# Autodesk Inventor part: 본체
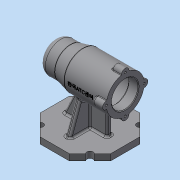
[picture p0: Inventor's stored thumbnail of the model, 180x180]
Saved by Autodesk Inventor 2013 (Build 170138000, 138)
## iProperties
Created: 2019-12
Part Number: 본체
Material: 일반
Document SubType Name: Modeling
Designer: Administrator
Density: 1 g/cm^3
Mass: 268.817 g
Surface Area: 714.69 cm^2
Volume: 268.817 cm^3
Author: Administrator
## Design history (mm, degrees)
sketch "스케치1"
  geometry: L1 (23.196, 56)-(56, 23.196); L2 (56, 23.196)-(56, -23.196); L3 (56, -23.196)-(23.196, -56); L4 (23.196, -56)-(-23.196, -56); L5 (-23.196, -56)-(-56, -23.196); L6 (-56, -23.196)-(-56, 23.196); L7 (-56, 23.196)-(-23.196, 56); L8 (-23.196, 56)-(23.196, 56); 3 further points
  constraints: 16 end point, 1 coincident, 1 midpoint, 1 vertical alignment, 17 other
  dimensions: "d2" = 56 distance from line of point (0, 0) L8
extrude "돌출1" new body sketch "스케치1" distance "d3" = 10; taper "d4" = 0 deg
sketch "스케치2"
  geometry: L1 (-56, 80)-(56, 80); L2 (-56, 0)-(-56, 10) reference; L3 (-56, 80)-(-56, 110); L4 (-56, 110)-(11, 110); L5 (11, 110)-(31, 105); L6 (31, 105)-(56, 105); L7 (56, 80)-(56, 105); 1 further point
  constraints: 12 end point, 2 perpendicular, 1 collinear, 1 horizontal, 1 parallel, 1 vertical alignment
  dimensions: "d5" = 112 distance of L1.start L1.end; "d7" = 80 vertical distance of point (0, 0) L1.start; "d8" = 50 diameter of L6 L1; "d9" = 60 diameter of L4 L1; "d10" = 45 horizontal distance of L1.end L4.end; "d11" = 25 horizontal distance of L1.end L5.end
revolve "회전1" sketch "스케치2" stored, may be unused: angle "d12" = 90 deg
sketch "스케치4"
  geometry: L1 (-23.196, -56)-(23.196, -56) reference; L2 (4, -36)-(-4, -36); L3 (-4, -36)-(-4, 36); L4 (-4, 36)-(4, 36); L5 (4, 36)-(4, -36); L6 (4, -36)-(-4, 36); L7 (-4, -36)-(4, 36); 3 further points
  constraints: 12 end point, 3 midpoint, 2 parallel, 1 coincident, 1 horizontal, 1 perpendicular
  dimensions: "d19" = 8 distance of L3.end L4.end; "d21" = 20 distance between parallel lines of L1 L2
extrude "돌출2" join sketch "스케치4" distance "d22" = 70; taper "d23" = 0 deg
feature "면 기울기1" dims angle "d24" = 20 deg
sketch "스케치5"
  geometry: L1 (-56, 23.196)-(-56, -23.196) reference; L2 (56, -23.196)-(56, 23.196) reference; L3 (-38, 4)-(31, 4); L4 (31, 4)-(31, -4); L5 (31, -4)-(-38, -4); L6 (-38, -4)-(-38, 4); 2 further points
  constraints: 8 end point, 2 parallel, 1 horizontal, 1 horizontal alignment, 1 midpoint, 1 perpendicular
  dimensions: "d25" = 18 distance between parallel lines of L1 L6; "d26" = 25 distance between parallel lines of L2 L4; "d27" = 8 distance between parallel lines of L3 L5
extrude "돌출3" join sketch "스케치5" distance "d28" = 70; taper "d29" = 0 deg
feature "면 기울기2" dims angle "d30" = 25 deg
sketch "스케치6"
  geometry: C1 r 30 at (0, 0) reference; C2 r 6 at (0, 30); 1 further point
  constraints: 1 centre point, 1 vertical alignment
  dimensions: "d31" = 12 diameter of C2; "d33" = 30 distance of C1.centre C2.centre
extrude "돌출4" join sketch "스케치6" distance "d34" = 16; taper "d35" = 0 deg
fillet "모깎기1" dims "d36" = 3
fillet "모깎기2" dims "d37" = 1
sketch "스케치7"
  geometry: A1 r 6 centre (0, 0) between (5.998, 0.171) and (-5.998, 0.171) reference; 2 further points
  constraints: 1 coincident
hole "구멍1" sketch "스케치7" at (0, 0) diameter "d38" = 3.242; stored, may be unused: countersink angle "d42" = 90 deg, drill point angle "d44" = 118 deg; dims "d39" = 8, "d40" = 4, "d41" = 2, "d43" = 11
node "작업 평면1"
sketch "스케치8"
  geometry: L1 (33.5, 29.226)-(33.5, 6.771) reference; L2 (33.5, 5.998)-(33.5, -5.998) reference; 3 further points
  constraints: 1 horizontal alignment, 1 midpoint, 1 other
  dimensions: "d48" = 41 distance from line of point (-7.5, 0) L1
feature "엠보싱1" sketch "스케치8" dims "d5" = 112, "d7" = 80, "d8" = 50, "d9" = 60, "d10" = 45, "d11" = 25, "d49" = 0.5, "d50" = 0
sketch "스케치9"
  geometry: L1 (56, -23.196)-(56, 23.196) reference; L2 (0, 0)-(-39.598, 39.598); L3 (0, 0)-(13.566, 0); C1 r 56 at (0, 0); 2 further points
  constraints: 4 end point, 2 coincident, 1 centre point, 1 perpendicular
  dimensions: "d51" = 112 diameter of C1; "d54" = 135 deg angle of L3 L2; "d56" = 56 distance of L2.start L2.end
hole "구멍2" sketch "스케치9" at (-39.598, 39.598) diameter "d57" = 10; stored, may be unused: countersink angle "d61" = 90 deg, drill point angle "d63" = 0 deg; dims "d58" = 8, "d59" = 4, "d60" = 2, "d62" = 11
hole "구멍3" diameter "d69" = 42; stored, may be unused: countersink angle "d73" = 90 deg, drill point angle "d75" = 0 deg; dims "d67" = 10, "d68" = 10, "d70" = 8, "d71" = 4, "d72" = 2, "d74" = 15
hole "구멍4" diameter "d78" = 48; stored, may be unused: countersink angle "d82" = 90 deg, drill point angle "d84" = 0 deg; dims "d76" = 10, "d77" = 10, "d79" = 8, "d80" = 4, "d81" = 2, "d83" = 54
hole "구멍5" diameter "d87" = 42; stored, may be unused: countersink angle "d91" = 90 deg, drill point angle "d93" = 0 deg; dims "d85" = 10, "d86" = 10, "d88" = 8, "d89" = 4, "d90" = 2, "d92" = 12
hole "구멍6" diameter "d96" = 35; stored, may be unused: countersink angle "d100" = 90 deg, drill point angle "d102" = 0 deg; dims "d94" = 10, "d95" = 10, "d97" = 8, "d98" = 4, "d99" = 2, "d101" = 18
hole "구멍7" diameter "d105" = 21; stored, may be unused: countersink angle "d109" = 90 deg, drill point angle "d111" = 0 deg; dims "d103" = 10, "d104" = 10, "d106" = 8, "d107" = 32, "d108" = 4, "d110" = 7
fillet "모깎기3" dims "d112" = 3
fillet "모깎기4" dims "d113" = 0.3
fillet "모깎기5" dims "d114" = 0.3
fillet "모깎기6" dims "d115" = 0.3
fillet "모깎기7" dims "d116" = 3
chamfer "모따기1" distance "d117" = 1; stored, may be unused: second distance "d118" = 2, angle "d119" = 45 deg
fillet "모깎기8" dims "d120" = 10
fillet "모깎기9" dims "d121" = 3
fillet "모깎기10" dims "d122" = 3
fillet "모깎기11" dims "d123" = 3
node "솔리드1"
pattern_circular "원형 패턴1" dims "d46" = 360 deg
pattern_circular "원형 패턴2" dims angle "d65" = 360 deg
